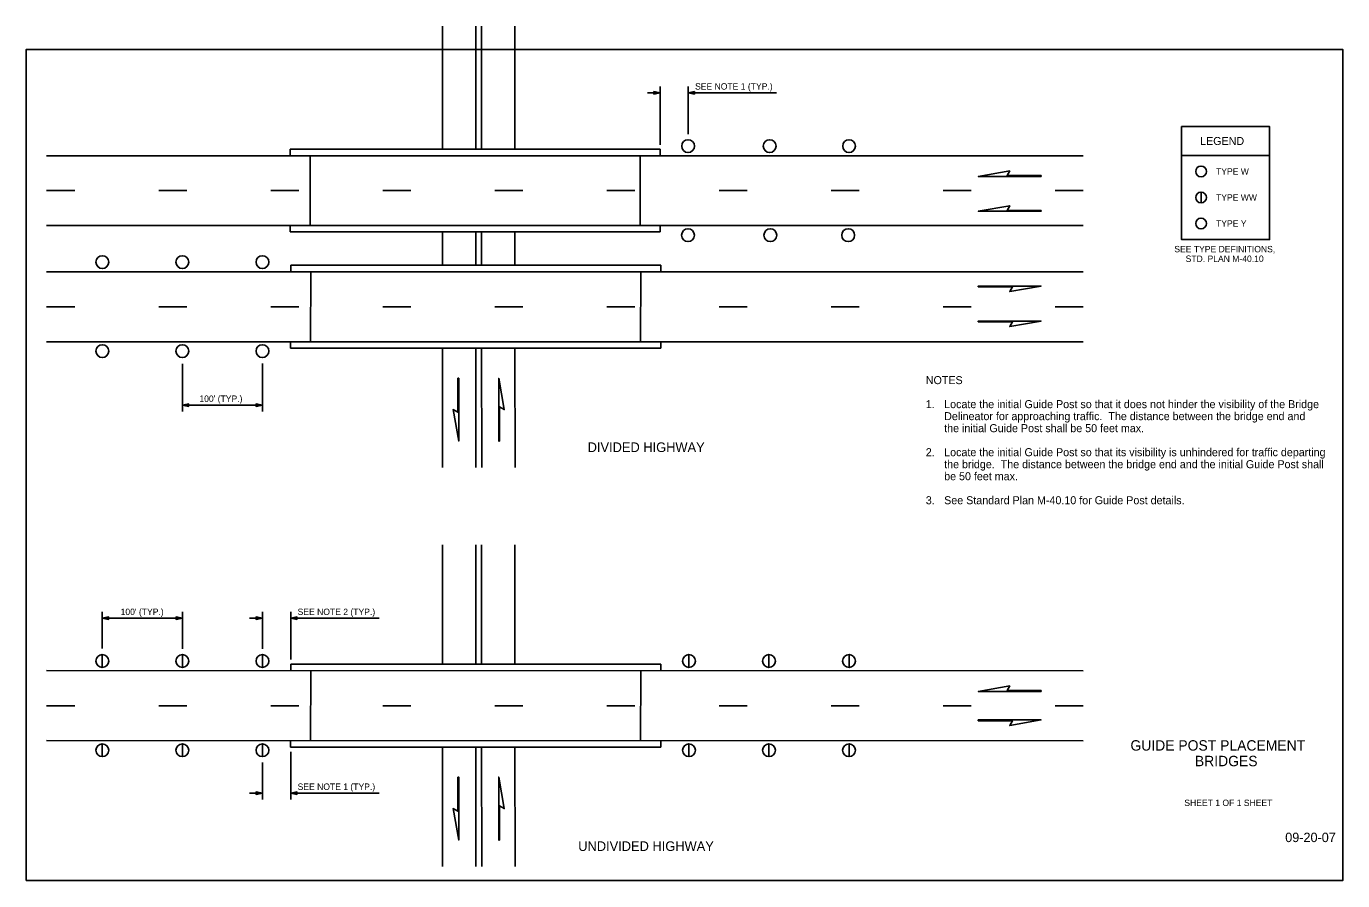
# Model space of a CAD drawing. Extents: x 99862 to 103151, y 100000 to 102133.
import ezdxf

# ---------------------------------------------------------------- set-up
doc = ezdxf.new("R2010")
doc.units = 0
for name, color, linetype in [('Level 1', 7, 'Continuous'), ('Level 11', 7, 'Continuous'), ('Level 15', 7, 'Continuous'), ('Level 20', 7, 'Continuous'), ('Level 3', 7, 'Continuous'), ('Level 4', 7, 'Continuous'), ('Level 40', 7, 'Continuous'), ('Level 5', 7, 'Continuous'), ('Level 60', 7, 'Continuous'), ('Level 62', 7, 'Continuous'), ('Level 9', 7, 'Continuous')]:
    doc.layers.add(name, color=color, linetype=linetype)

msp = doc.modelspace()

# ---------------------------------------------------------------- linework, layer by layer
at = {"layer": 'Level 1'}
msp.add_lwpolyline([(99862, 99999.5), (103151, 99999.5), (103151, 102075.5), (99862, 102075.5)], close=True, dxfattribs=at)
at = {"layer": 'Level 11'}
for p, q in [((100521.5, 101810.1), (100521.6, 101826.1)), ((100521.6, 101826.1), (101445.8, 101826)), ((100571.2, 101635.6), (100571.5, 101810.1)), ((101395.8, 101810), (101395.8, 101635.6)), ((101445.8, 101826), (101445.8, 101810)), ((100521.2, 101619.6), (100521.2, 101635.6)), ((101445.8, 101635.6), (101445.8, 101619.6)), ((101445.8, 101619.6), (100521.2, 101619.6)), ((100522.5, 101536.3), (101447, 101536.3)), ((100522.5, 101520.3), (100522.5, 101536.3)), ((101447.1, 101520.3), (101447, 101536.3)), ((100572.2, 101345.5), (100572.5, 101520.3)), ((101396.9, 101345.5), (101397.1, 101520.3)), ((100522.1, 101329.5), (100522.2, 101345.5)), ((101447.4, 101329.5), (101447.4, 101345.5)), ((101447.4, 101329.5), (100522.1, 101329.5)), ((100522.5, 100540), (101447, 100539.9)), ((100522.5, 100524), (100522.5, 100540)), ((100572.2, 100349.2), (100572.5, 100524)), ((101396.9, 100349.1), (101397.1, 100523.9)), ((101447.1, 100523.9), (101447, 100539.9)), ((100522.1, 100333.2), (100522.2, 100349.2)), ((101447.4, 100333.1), (101447.4, 100349.1)), ((101447.4, 100333.1), (100522.1, 100333.2))]:
    msp.add_line(p, q, dxfattribs=at)
at = {"layer": 'Level 15'}
for p, q in [((101413.8, 101967.2), (101445.8, 101967.2)), ((101445.8, 101836.9), (101445.8, 101983.2)), ((101515.5, 101864.2), (101515.5, 101983.2)), ((101515.5, 101967.2), (101736.6, 101967.2)), ((100251.9, 101290.2), (100251.9, 101171.2)), ((100452, 101291.3), (100452, 101171.2)), ((100251.9, 101187.2), (100452, 101187.2)), ((100051.9, 100579.4), (100051.9, 100671)), ((100051.9, 100655), (100251.9, 100655)), ((100251.9, 100578.3), (100251.9, 100671)), ((100420, 100655), (100452, 100655)), ((100452, 100578.2), (100452, 100671)), ((100522.5, 100552), (100522.5, 100670.9)), ((100522.5, 100654.9), (100743.5, 100654.9)), ((100522.5, 100321.2), (100522.5, 100202.2)), ((100452, 100294.9), (100452, 100202.2)), ((100420, 100218.2), (100452, 100218.2)), ((100522.5, 100218.2), (100743.5, 100218.2))]:
    msp.add_line(p, q, dxfattribs=at)
for points in [[(101445.8, 101967.2), (101430.1, 101970.3), (101430.8, 101967.2), (101430.1, 101964.1)], [(101515.5, 101967.2), (101531.2, 101964.1), (101530.5, 101967.2), (101531.2, 101970.3)], [(100251.9, 101187.2), (100267.6, 101190.3), (100266.9, 101187.2), (100267.6, 101184.1)], [(100452, 101187.2), (100436.2, 101184.1), (100437, 101187.2), (100436.2, 101190.3)], [(100051.9, 100655), (100067.6, 100651.9), (100066.9, 100655), (100067.6, 100658.1)], [(100251.9, 100655), (100236.2, 100658.1), (100236.9, 100655), (100236.2, 100651.9)], [(100452, 100655), (100436.2, 100658.1), (100437, 100655), (100436.2, 100651.9)], [(100522.5, 100654.9), (100538.2, 100651.9), (100537.5, 100654.9), (100538.2, 100658)], [(100452, 100218.2), (100436.2, 100215.1), (100437, 100218.2), (100436.2, 100221.3)], [(100522.5, 100218.2), (100538.2, 100221.3), (100537.5, 100218.2), (100538.2, 100215.1)]]:
    msp.add_lwpolyline(points, close=True, dxfattribs=at)
at = {"layer": 'Level 20'}
msp.add_line((102797.1, 101719.2), (102797.1, 101692.3), dxfattribs=at)
for centre in [(102797.2, 101770.8), (102797.2, 101705.8), (102797.2, 101640.8), (102797.2, 101640.8)]:
    msp.add_circle(centre, 13.4, dxfattribs=at)
at = {"layer": 'Level 3'}
for points in [[(102397.6, 101760.7), (102312.3, 101760.7), (102319, 101772.3), (102240.5, 101758.5), (102397.6, 101758.5)], [(102397.6, 101673.4), (102312.3, 101673.4), (102319, 101685.1), (102240.5, 101671.2), (102397.6, 101671.2)], [(102240.5, 101482.3), (102325.8, 101482.3), (102319, 101470.7), (102397.6, 101484.6), (102240.5, 101484.6)], [(102240.5, 101394.9), (102325.8, 101394.9), (102319, 101383.3), (102397.6, 101397.1), (102240.5, 101397.1)], [(100940.1, 101254.4), (100940.1, 101169.2), (100928.4, 101175.9), (100942.3, 101097.3), (100942.3, 101254.4)], [(101044.5, 101097.3), (101044.5, 101182.6), (101056.1, 101175.9), (101042.3, 101254.4), (101042.3, 101097.3)], [(102397.6, 100474.3), (102312.3, 100474.3), (102319, 100486), (102240.5, 100472.1), (102397.6, 100472.1)], [(102240.5, 100398.5), (102325.8, 100398.5), (102319, 100386.9), (102397.6, 100400.8), (102240.5, 100400.8)], [(100940.1, 100258.1), (100940.1, 100172.8), (100928.4, 100179.5), (100942.3, 100100.9), (100942.3, 100258.1)], [(101044.5, 100100.9), (101044.5, 100186.2), (101056.1, 100179.5), (101042.3, 100258.1), (101042.3, 100100.9)]]:
    msp.add_lwpolyline(points, close=True, dxfattribs=at)
at = {"layer": 'Level 4'}
for p, q in [((100901.8, 101826), (100901.8, 102133.2)), ((101082.5, 102133.2), (101082.7, 101826)), ((102502.8, 101810.1), (99912.8, 101810.1)), ((102502.8, 101635.6), (99912.8, 101635.6)), ((100901.8, 101619.6), (100901.8, 101536.3)), ((101082.6, 101536.3), (101082.6, 101619.6)), ((99912.8, 101520.4), (102502.8, 101520.2)), ((102502.8, 101345.4), (99912.8, 101345.6)), ((100901.9, 101329.5), (100902.1, 101031.2)), ((101082.9, 101329.5), (101083.1, 101031.2)), ((100901.5, 100838.3), (100901.6, 100540)), ((101082.4, 100838.3), (101082.6, 100539.9)), ((99912.8, 100524), (102502.8, 100523.9)), ((102502.8, 100349), (99912.8, 100349.2)), ((100901.9, 100333.1), (100902.1, 100034.8)), ((101082.9, 100333.1), (101083.1, 100034.8))]:
    msp.add_line(p, q, dxfattribs=at)
at = {"layer": 'Level 40'}
msp.add_lwpolyline([(102748.3, 101882.8), (102968.3, 101882.8), (102968.3, 101810.8), (102748.3, 101810.8)], close=True, dxfattribs=at)
msp.add_lwpolyline([(102748.3, 101810.8), (102748.3, 101600.8), (102968.3, 101600.8), (102968.3, 101810.8), (102748.3, 101810.8)], dxfattribs=at)
at = {"layer": 'Level 5'}
for p, q in [((100985, 101826), (100984.8, 102133.2)), ((100999.4, 101826), (100999.2, 102133.2)), ((99982.8, 101722.9), (99912.8, 101722.9)), ((100262.8, 101722.9), (100192.8, 101722.9)), ((100542.8, 101722.9), (100472.8, 101722.9)), ((100822.8, 101722.9), (100752.8, 101722.9)), ((101102.8, 101722.9), (101032.8, 101722.9)), ((101382.8, 101722.9), (101312.8, 101722.9)), ((101662.8, 101722.9), (101592.8, 101722.9)), ((101942.8, 101722.9), (101872.8, 101722.9)), ((102222.8, 101722.9), (102152.8, 101722.9)), ((102502.8, 101722.9), (102432.8, 101722.9)), ((100985.1, 101536.3), (100985.1, 101619.6)), ((100999.5, 101536.3), (100999.5, 101619.6)), ((99982.8, 101432.8), (99912.8, 101432.8)), ((100262.8, 101432.8), (100192.8, 101432.8)), ((100542.8, 101432.8), (100472.8, 101432.8)), ((100822.8, 101432.8), (100752.8, 101432.8)), ((101102.8, 101432.8), (101032.8, 101432.8)), ((101382.8, 101432.8), (101312.8, 101432.8)), ((101662.8, 101432.8), (101592.8, 101432.8)), ((101942.8, 101432.8), (101872.8, 101432.8)), ((102222.8, 101432.8), (102152.8, 101432.8)), ((102502.8, 101432.8), (102432.8, 101432.8)), ((100985.4, 101031.2), (100985.2, 101329.5)), ((100999.8, 101031.2), (100999.6, 101329.5)), ((100984.9, 100539.9), (100984.8, 100838.3)), ((100999.3, 100539.9), (100999.2, 100838.3)), ((99982.8, 100436.4), (99912.8, 100436.4)), ((100262.8, 100436.4), (100192.8, 100436.4)), ((100542.8, 100436.4), (100472.8, 100436.4)), ((100822.8, 100436.4), (100752.8, 100436.4)), ((101102.8, 100436.4), (101032.8, 100436.4)), ((101382.8, 100436.4), (101312.8, 100436.4)), ((101662.8, 100436.4), (101592.8, 100436.4)), ((101942.8, 100436.4), (101872.8, 100436.4)), ((102222.8, 100436.4), (102152.8, 100436.4)), ((102502.8, 100436.4), (102432.8, 100436.4)), ((100985.4, 100034.8), (100985.2, 100333.1)), ((100999.8, 100034.8), (100999.6, 100333.1))]:
    msp.add_line(p, q, dxfattribs=at)
at = {"layer": 'Level 60'}
for p, q in [((103151, 102075.5), (103151, 102075.5)), ((99862, 99999.5), (99862, 99999.5))]:
    msp.add_line(p, q, dxfattribs=at)
at = {"layer": 'Level 9'}
for p, q in [((100051.9, 100564), (100051.9, 100532)), ((100251.9, 100564), (100251.9, 100532)), ((100452, 100564), (100452, 100532)), ((101517.6, 100564), (101517.6, 100532)), ((101717.6, 100564), (101717.6, 100532)), ((101917.6, 100564), (101917.6, 100532)), ((100051.9, 100341.2), (100051.9, 100309.2)), ((100251.9, 100341.2), (100251.9, 100309.2)), ((100452, 100341.2), (100452, 100309.2)), ((101517.6, 100341.2), (101517.6, 100309.2)), ((101717.6, 100341.2), (101717.6, 100309.2)), ((101917.6, 100341.2), (101917.6, 100309.2))]:
    msp.add_line(p, q, dxfattribs=at)
for centre in [(101515.5, 101834), (101719.2, 101834), (101917.7, 101834), (101515.4, 101611.6), (101721, 101611.6), (101915.5, 101611.6), (100051.9, 101544.3), (100251.9, 101544.3), (100452, 101544.3), (100051.9, 101322), (100251.9, 101322), (100452, 101322), (100051.9, 100548), (100251.9, 100548), (100452, 100548), (101517.6, 100548), (101717.6, 100548), (101917.6, 100548), (100051.9, 100325.2), (100251.9, 100325.2), (100452, 100325.2), (101517.6, 100325.2), (101717.6, 100325.2), (101917.6, 100325.2)]:
    msp.add_circle(centre, 16, dxfattribs=at)

# ---------------------------------------------------------------- texts
at = {"layer": 'Level 20'}
for s, height, p in [('SEE NOTE 1 (TYP.)', 16, (101532.9, 101975.2)), ('LEGEND', 20, (102794.8, 101836.8)), ('TYPE W', 16, (102834.6, 101762.8)), ('TYPE WW', 16, (102834.6, 101697.8)), ('TYPE Y', 16, (102834.6, 101632.8)), ('SEE TYPE DEFINITIONS,', 16, (102730.4, 101568.8)), ('STD. PLAN M-40.10', 16, (102758.6, 101544.8)), ('NOTES', 20, (102109.4, 101239.6)), ("100' (TYP.)", 16, (100294.4, 101195.2)), ('1.', 20, (102109.4, 101179.6)), ('Locate the initial Guide Post so that it does not hinder the visibility of the Bridge', 20, (102155.3, 101179.6)), ('Delineator for approaching traffic.  The distance between the bridge end and', 20, (102155.3, 101149.6)), ('the initial Guide Post shall be 50 feet max.', 20, (102155.3, 101119.6)), ('DIVIDED HIGHWAY', 24, (101264.5, 101070)), ('2.', 20, (102109.4, 101059.6)), ('Locate the initial Guide Post so that its visibility is unhindered for traffic departing', 20, (102155.3, 101059.6)), ('the bridge.  The distance between the bridge end and the initial Guide Post shall', 20, (102155.3, 101029.6)), ('be 50 feet max.', 20, (102155.3, 100999.6)), ('3.', 20, (102109.4, 100939.6)), ('See Standard Plan M-40.10 for Guide Post details.', 20, (102155.3, 100939.6)), ("100' (TYP.)", 16, (100097.6, 100663)), ('SEE NOTE 2 (TYP.)', 16, (100539.8, 100662.9)), ('SEE NOTE 1 (TYP.)', 16, (100539.8, 100226.2)), ('UNDIVIDED HIGHWAY', 24, (101241, 100073.7))]:
    msp.add_text(s, height=height, dxfattribs=at).set_placement(p)
at = {"layer": 'Level 62'}
for s, height, p in [('GUIDE POST PLACEMENT', 26, (102620.7, 100324.3)), ('BRIDGES', 26, (102781.8, 100285.3)), ('SHEET 1 OF 1 SHEET', 16, (102755.4, 100185.9)), ('09-20-07', 23.62, (103007.4, 100095.8))]:
    msp.add_text(s, height=height, dxfattribs=at).set_placement(p)

doc.saveas('drawing.dxf')
